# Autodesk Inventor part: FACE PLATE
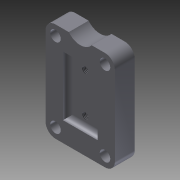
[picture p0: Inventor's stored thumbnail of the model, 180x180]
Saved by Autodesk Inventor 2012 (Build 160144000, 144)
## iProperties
Shininess: 64.0
Length Units: 11272
Angle Units: 11279
Time Units: 11290
Mass Units: 11286
Length Display Precision: 3
Angle Display Precision: 2
Compacted: True
Part Number: FACE PLATE
Document SubType Name: Modeling
Created: 2003-11
Designer: Autodesk, Inc.
Manufacturer: Standard
Standards Organization: Custom
Mass: 239.386 g
Surface Area: 93.2455 cm^2
Volume: 30.4562 cm^3
Density: 7.86 g/cm^3
Material: Steel, Mild
Density: 0.0
Volumn: 0.0
Area: 0.0
PropertySet Name: Model Information
Control State: 0
Master: False
Checked Out: False
Author: Autodesk, Inc.
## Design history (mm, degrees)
sketch "Sketch1"
  geometry: L1 (0, 0)-(44.45, 0); L2 (44.45, 0)-(44.45, 63.5); L3 (44.45, 63.5)-(0, 63.5); L4 (0, 63.5)-(0, 0)
  constraints: 8 end point, 2 parallel, 1 horizontal, 1 perpendicular
  dimensions: "d0" = 44.45 distance between parallel lines of L2 L4; "d1" = 63.5 distance of L1.end L2.end
extrude "Extrusion1" new body sketch "Sketch1" distance "d2" = 12.7; taper "d3" = 0 deg
sketch "Sketch2"
  geometry: L1 (0, 0)-(0, 63.5) reference; L2 (44.45, 0)-(0, 0) reference; L3 (44.45, 63.5)-(44.45, 0) reference; L4 (0, 63.5)-(44.45, 63.5) reference; L5 (0, 31.75)-(44.45, 31.75); 4 further points
  constraints: 2 end point, 2 midpoint, 2 symmetric about line
  dimensions: "d4" = 6.35 distance from line of point (6.35, 57.15) L4; "d5" = 6.35 distance from line of L4 point (38.1, 57.15); "d6" = 6.35 distance from line of L1 point (6.35, 57.15); "d7" = 6.35 distance from line of L3 point (38.1, 57.15)
hole "Hole1" sketch "Sketch2" at (6.35, 57.15), (38.1, 57.15), (6.35, 6.35), (38.1, 6.35) diameter "d8" = 6.731; stored, may be unused: countersink angle "d12" = 82 deg, drill point angle "d14" = 118 deg; dims "d9" = 12.7, "d10" = 9.525, "d11" = 6.35, "d13" = 19.05
fillet "Fillet1" dims "d15" = 6.35
sketch "Sketch3"
  geometry: L1 (11.125, 50.8)-(33.35, 50.8); L2 (33.35, 50.8)-(33.35, 12.7); L3 (33.35, 12.7)-(11.125, 12.7); L4 (11.125, 12.7)-(11.125, 50.8); L5 (44.45, 57.15)-(44.45, 6.35) reference; L6 (38.1, 0)-(6.35, 0) reference
  constraints: 8 end point, 2 parallel, 1 horizontal, 1 perpendicular
  dimensions: "d16" = 11.0998 distance between parallel lines of L5 L2; "d17" = 22.225 distance between parallel lines of L2 L4; "d18" = 12.7 distance between parallel lines of L6 L3; "d19" = 38.1 distance between parallel lines of L3 L1
extrude "Extrusion2" cut sketch "Sketch3" distance "d20" = 3.175; taper "d21" = 0 deg
sketch "Sketch4"
  geometry: L1 (14.3, 15.875)-(14.3, 47.625) reference; L2 (30.175, 47.625)-(30.175, 15.875) reference; L3 (14.3, 47.625)-(30.175, 47.625) reference; L4 (14.3, 31.75)-(30.175, 31.75); L5 (30.175, 15.875)-(14.3, 15.875) reference; C1 r 3.365 at (6.35, 57.15) reference; 1 further point
  constraints: 2 end point, 2 midpoint
  dimensions: "d23" = 15.875 horizontal distance of C1.centre point (22.225, 44.45); "d24" = 12.7 vertical distance of point (22.225, 44.45) C1.centre
hole "Hole2" sketch "Sketch4" at (22.225, 44.45) diameter "d25" = 3.9624; stored, may be unused: countersink angle "d29" = 82 deg, drill point angle "d31" = 118 deg; dims "d26" = 12.7, "d27" = 9.525, "d28" = 6.35, "d30" = 19.05
workplane "Work Plane1"
mirror "Mirror1"
sketch "Sketch5"
  geometry: C1 r 9.274 at (-22.225, 69.17)
  constraints: 1 centre point
extrude "Extrusion3" cut sketch "Sketch5" stored distance "d33" = 25.4; taper "d34" = 0 deg
fillet "Fillet3" dims "d39" = 3.175
body "Solid1"
node "Projected Loop1"
other parameters: "d32" = -31.75, "d35" = 0, "d36" = 0, "d37" = 0, "d38" = 0
